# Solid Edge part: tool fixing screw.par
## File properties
Author: Deepak Maini
Template: Normal.par
Last saved by: Robert a Rhodes jr
Revision: 7
Application: Solid Edge
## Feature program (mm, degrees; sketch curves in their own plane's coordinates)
sketch for "unnamed RevolvedProtrusion 1" plane through (0, 0, 0) normal (0, -1, 0) x-axis (1, 0, 0)
  line (0, 32.784) -> (7, 32.784)
  line (7, 32.784) -> (7, 22.784)
  line (7, 22.784) -> (14, 22.784)
  line (14, 22.784) -> (14, 18.784)
  line (14, 18.784) -> (8, 18.784)
  line (8, 18.784) -> (8, -27.216)
  line (8, -27.216) -> (7, -27.216)
  line (7, -27.216) -> (7, -37.216)
  line (7, -37.216) -> (0, -37.216)
  line (0, 32.784) -> (0, -37.216)
revolve "unnamed RevolvedProtrusion 1" add full turn 360 deg
sketch for "unnamed Protrusion 1" plane through (0, 0, 0) normal (0, -1, 0) x-axis (1, 0, 0)
  line (-8, 48.784) -> (-8, 32.784)
  line (-8, 32.784) -> (8, 32.784)
  line (8, 32.784) -> (8, 48.784)
  line (8, 48.784) -> (-8, 48.784)
extrude "unnamed Protrusion 1" add finite 16 symmetric
sketch for "unnamed RevolvedCutout 1" #1 plane through (3.6, -3.6, 33.784) normal (-0.707107, -0.707107, 0) x-axis (-0.707107, 0.707107, 0)
  arc centre (12.3381, -3.0322) radius 4.0668 from (12.8672, 1) to (16.4049, -3.0322) cw
  line (18.5702, -3.0322) -> (16.4049, -3.0322)
  line (18.5702, 3.0753) -> (18.5702, -3.0322)
  line (12.8672, 3.0753) -> (18.5702, 3.0753)
  line (12.8672, 1) -> (12.8672, 3.0753)
sketch for "unnamed RevolvedCutout 1" #2 plane through (3.6, -3.6, 33.784) normal (-0.707107, -0.707107, 0) x-axis (-0.707107, 0.707107, 0)
  arc centre (12.3381, -10.9332) radius 4.0668 from (12.3381, -15) to (16.3999, -10.733) ccw
  line (18.7725, -10.9332) -> (16.3999, -10.733)
  line (18.7725, -17.6337) -> (18.7725, -10.9332)
  line (12.584, -17.6337) -> (18.7725, -17.6337)
  line (12.3381, -15) -> (12.584, -17.6337)
revolve "unnamed RevolvedCutout 1" cut full turn 360 deg
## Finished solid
Body 1: solid body, 24 faces, 42 edges, 20 vertices.
  Faces by surface: plane 10, torus 6, cone 4, cylinder 4
  Edges by curve: intersection 24, circle 14, line 4
Bounding box of the edges (mm; curved faces can reach further): 28.000 x 28.000 x 86.000, from (-14, -14, -37.216) to (14, 14, 48.784).
Cylindrical faces by radius (mm): R7 x2, R8 x1, R14 x1
Conical faces (half-angle, radius in mm at the cone's reference point): 85.1753 deg R11.3088 x4
Toroidal faces (ring radius, tube radius in mm): R7.247 r4.0668 x6
Planar faces by outward normal: +x 1, +y 1, +z 2, -x 1, -y 1, -z 4
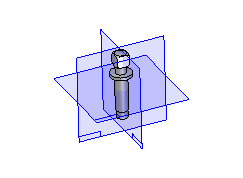
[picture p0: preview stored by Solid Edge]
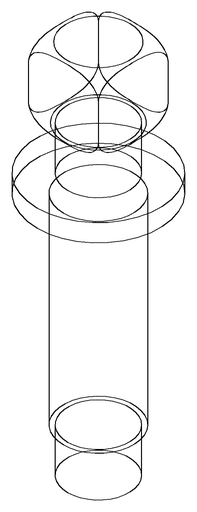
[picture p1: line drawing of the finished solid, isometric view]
